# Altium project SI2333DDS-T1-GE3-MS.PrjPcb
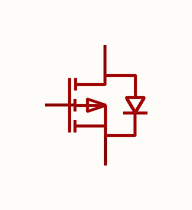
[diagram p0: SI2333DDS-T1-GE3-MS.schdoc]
1 sheet, 1 parts. Net scope: global (net labels, ports and power ports of the same name join across sheets).

## Sheet SI2333DDS-T1-GE3-MS.schdoc
size 127 x 101 mm

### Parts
Q?  si2333dds-t1-ge3-ms  [SOT-23-3_L2.9-W1.3-P1.90-LS2.4-BR]  (value not drawn)

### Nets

Not connected (* = marked no-connect by the designer): Q? 1(G) 2(S) 3(D)

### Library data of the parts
Q? = si2333dds-t1-ge3-ms: 数量:1个P沟道;漏源电压(Vdss):12V;连续漏极电流(Id):5.5A;导通电阻(RDS(on)):25mΩ@4.5V;耗散功率(Pd):1.56W;阈值电压(Vgs(th)):600mV;; Manufacturer: MSKSEMI(美森科); AddInBom: yes; ModelId: c62791f0466c4ae2a892c056b845b0ca; ModelName: SOT-23-3P_L2.9-W1.3-H1.0-LS2.4-P0.95; ModelTransform: 98.425,114.173,0,180,0,0,0.0005,-0.0005,0; Number: 1个P沟道; Drain to Source Voltage: 12V; Current - Continuous Drain(Id): 5.5A; Pd - Power Dissipation: 1.56W; Gate Threshold Voltage (Vgs(th)): 600mV; Gate Charge(Qg): 16.1nC@4.5V; Input Capacitance(Ciss): 1.44nF; Reverse Transfer Capacitance (Crss@Vds): 115pF; Type: P沟道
